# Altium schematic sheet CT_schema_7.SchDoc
size 430 x 429 mm
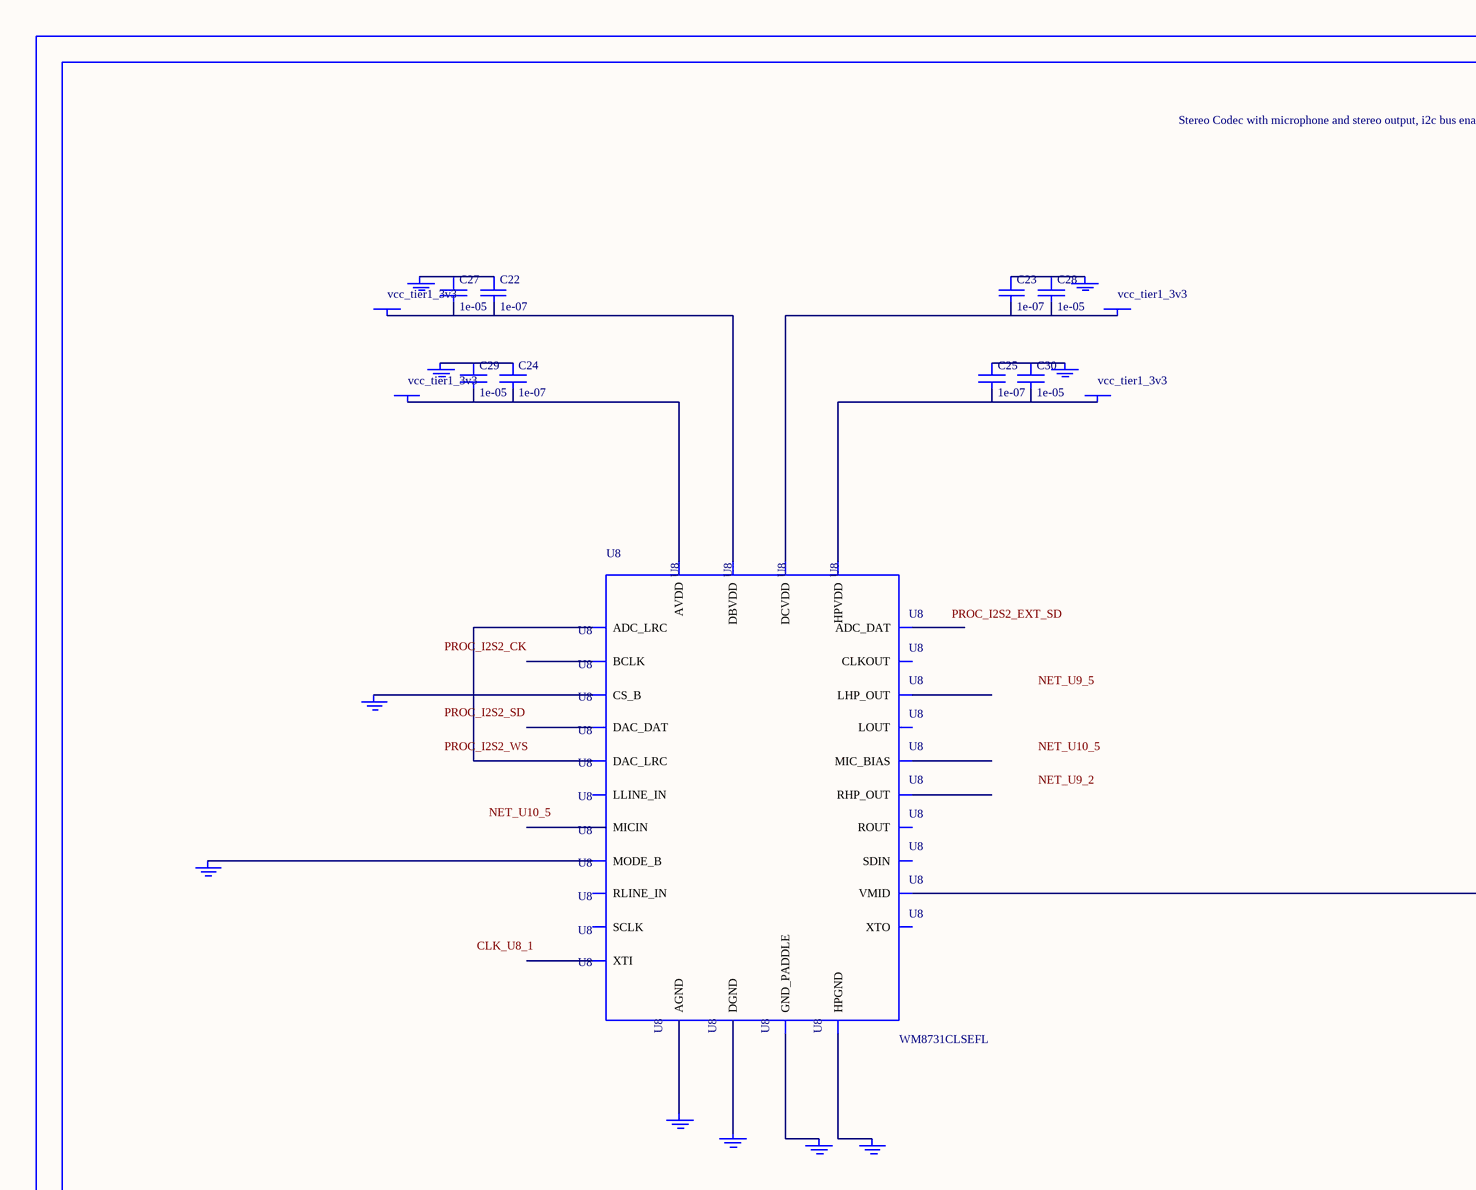
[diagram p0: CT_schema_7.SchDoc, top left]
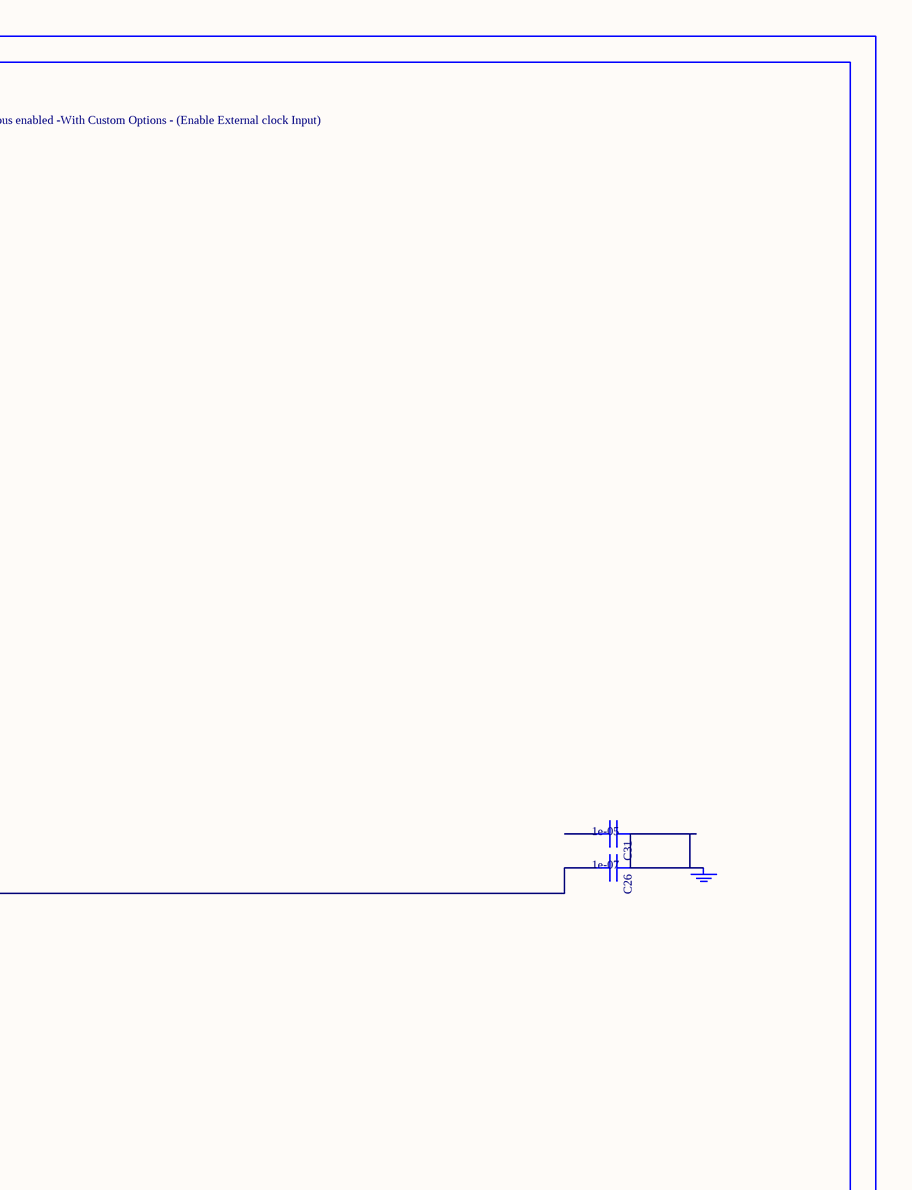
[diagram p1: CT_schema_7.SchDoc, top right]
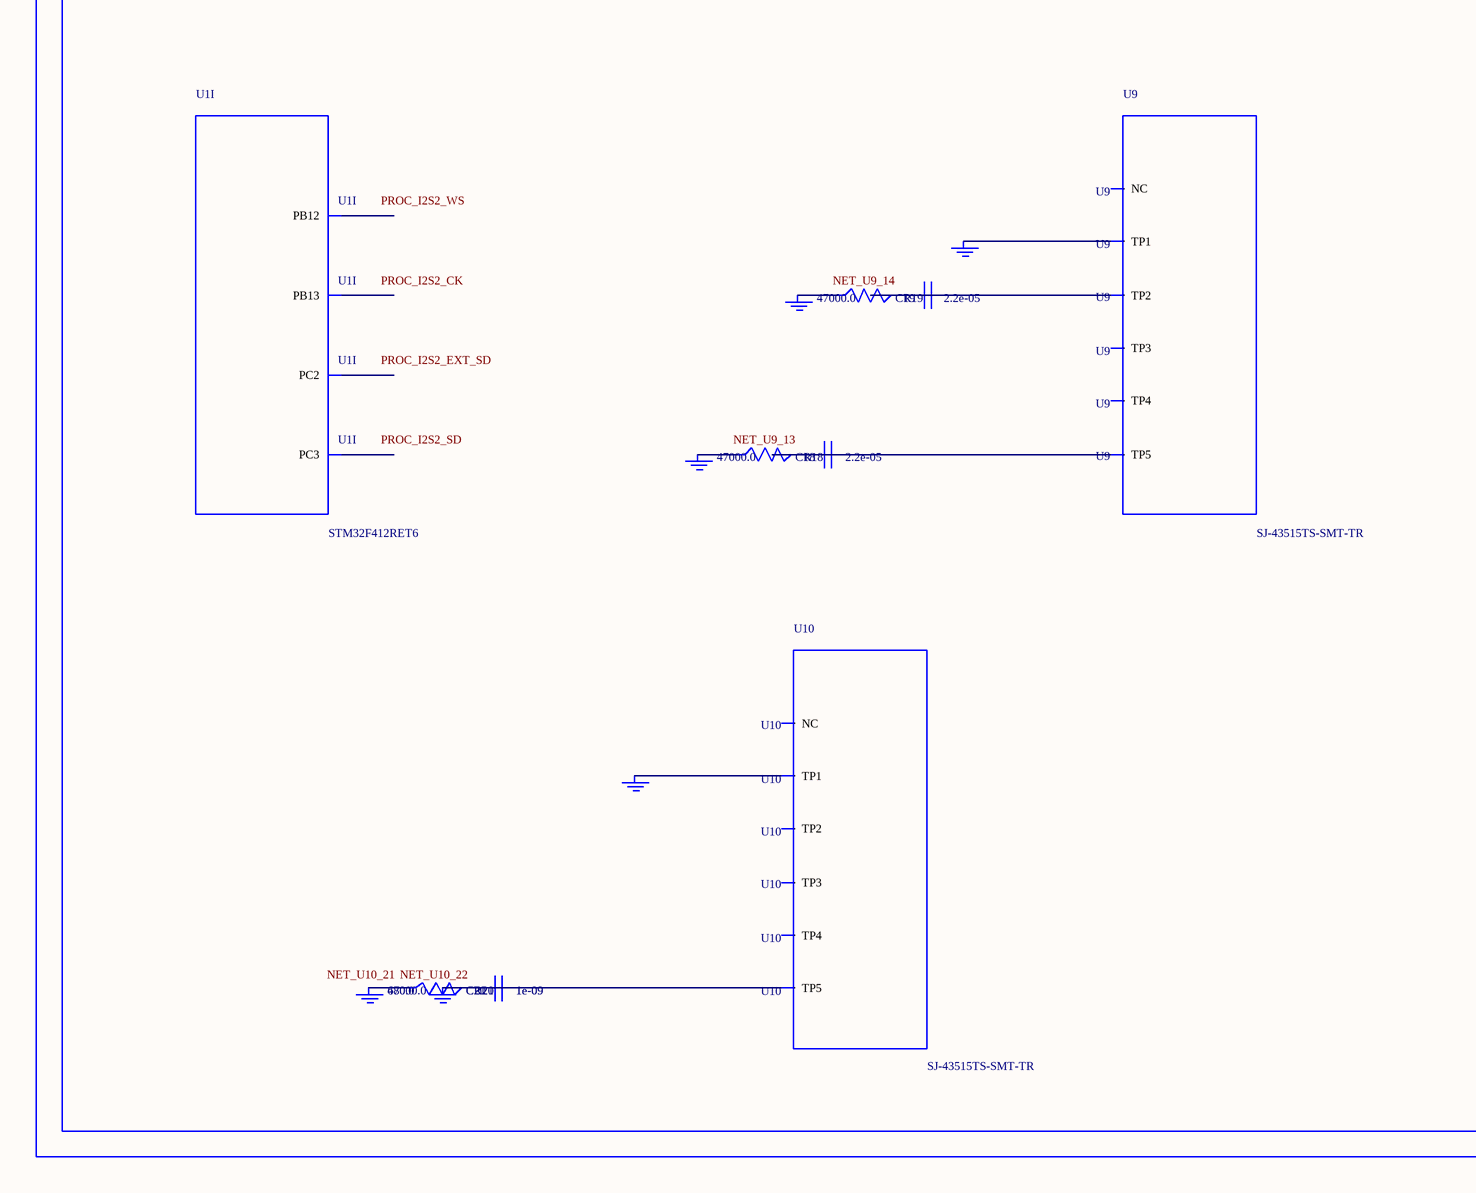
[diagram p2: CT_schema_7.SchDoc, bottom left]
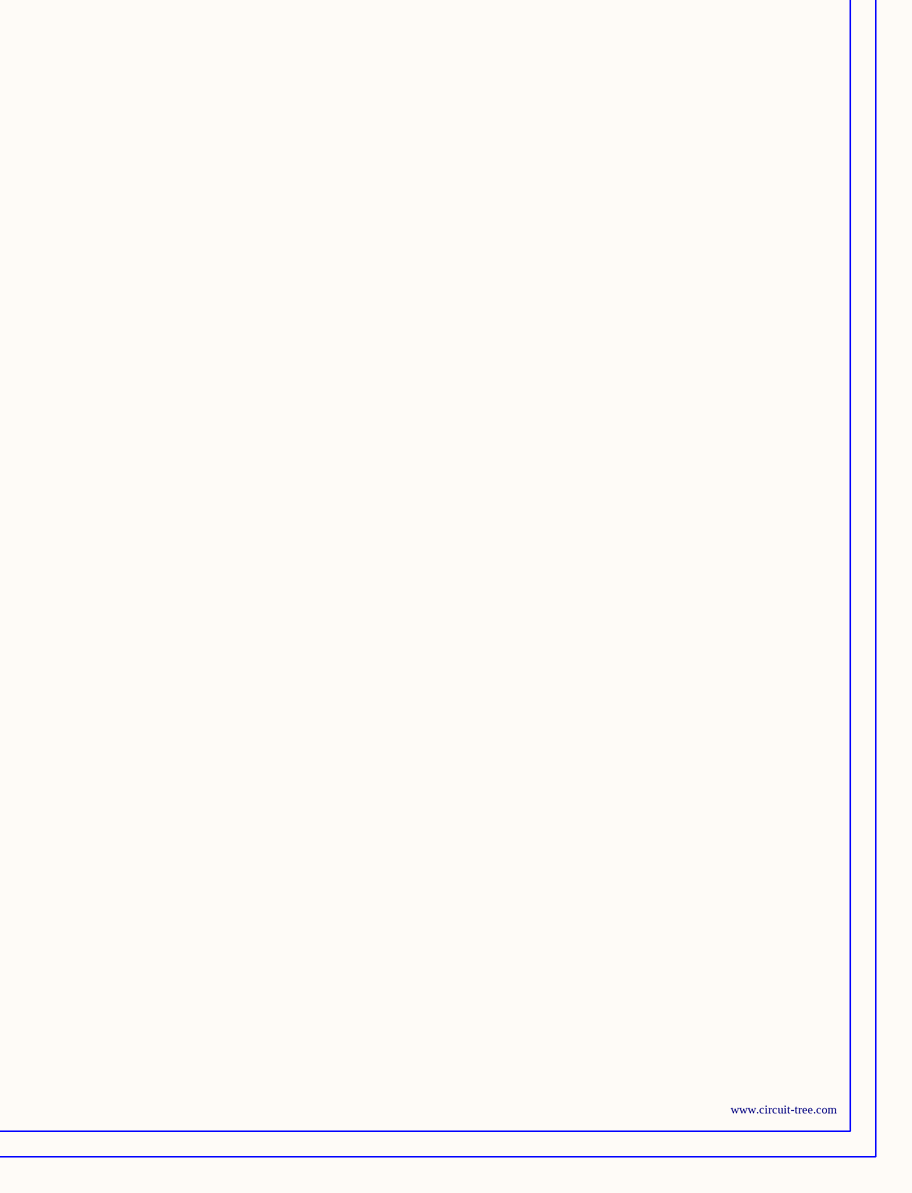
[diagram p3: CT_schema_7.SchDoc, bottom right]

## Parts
BORDER6  (no value)
C18  2.2e-05  [C1210]
C19  2.2e-05  [C1210]
C20  1e-09  [C0402]
C21  1e-09  [C0402]
C22  1e-07  [C0402]
C23  1e-07  [C0402]
C24  1e-07  [C0402]
C25  1e-07  [C0402]
C26  1e-07  [C0402]
C27  1e-05  [C0805]
C28  1e-05  [C0805]
C29  1e-05  [C0805]
C30  1e-05  [C0805]
C31  1e-05  [C0805]
GND_INSTANCE_6_0  (no value)
GND_INSTANCE_6_1  (no value)
GND_INSTANCE_6_2  (no value)
GND_INSTANCE_6_3  (no value)
GND_INSTANCE_6_4  (no value)
GND_INSTANCE_6_5  (no value)
GND_INSTANCE_6_6  (no value)
GND_INSTANCE_6_7  (no value)
GND_INSTANCE_6_8  (no value)
GND_INSTANCE_6_9  (no value)
GND_INSTANCE_6_10  (no value)
GND_INSTANCE_6_11  (no value)
GND_INSTANCE_6_12  (no value)
GND_INSTANCE_6_13  (no value)
GND_INSTANCE_6_14  (no value)
GND_INSTANCE_6_15  (no value)
GND_INSTANCE_6_16  (no value)
POWER_INSTANCE_6_0  vcc_tier1_3v3
POWER_INSTANCE_6_1  vcc_tier1_3v3
POWER_INSTANCE_6_2  vcc_tier1_3v3
POWER_INSTANCE_6_3  vcc_tier1_3v3
R18  47000.0  [R0603]
R19  47000.0  [R0603]
R20  47000.0  [R0603]
R21  680.0  [R0603]
U1  STM32F412RET6  [LQFP64]  (part I of 9)
U8  WM8731CLSEFL  [QFN-28]
U9  SJ-43515TS-SMT-TR  [SJ-43515TS-SMT-TR]
U10  SJ-43515TS-SMT-TR  [SJ-43515TS-SMT-TR]

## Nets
NetC18_1: C18.1 C18.2 R18.2 U9.5(TP5)
NetC19_1: C19.1 C19.2 R19.2 U9.2(TP2)
NetC20_1: C20.1 C20.2 C21.1 C21.2 GND_INSTANCE_6_16.0(GND) R20.2 R21.2 U10.5(TP5)
NetC22_1: C22.1 C27.1 GND_INSTANCE_6_1.0(GND)
NetC22_2: C22.2 C27.2 POWER_INSTANCE_6_1.0(PWR) U8.5(DBVDD)
NetC23_1: C23.1 C28.1 GND_INSTANCE_6_0.0(GND)
NetC23_2: C23.2 C28.2 POWER_INSTANCE_6_0.0(PWR) U8.3(DCVDD)
NetC24_1: C24.1 C29.1 GND_INSTANCE_6_4.0(GND)
NetC24_2: C24.2 C29.2 POWER_INSTANCE_6_3.0(PWR) U8.18(AVDD)
NetC25_1: C25.1 C30.1 GND_INSTANCE_6_2.0(GND)
NetC25_2: C25.2 C30.2 POWER_INSTANCE_6_2.0(PWR) U8.12(HPVDD)
NetC26_1: C26.1 C31.1 GND_INSTANCE_6_5.0(GND)
NetC26_2: C26.2 U8.20(VMID)
NetGND_INSTANCE_6_3_0: GND_INSTANCE_6_3.0(GND) U8.15(HPGND)
NetGND_INSTANCE_6_6_0: GND_INSTANCE_6_6.0(GND) U8.25(MODE_B)
NetGND_INSTANCE_6_7_0: GND_INSTANCE_6_7.0(GND) U8.26(CS_B)
NetGND_INSTANCE_6_8_0: GND_INSTANCE_6_8.0(GND) U8.29(GND_PADDLE)
NetGND_INSTANCE_6_9_0: GND_INSTANCE_6_9.0(GND) U8.4(DGND)
NetGND_INSTANCE_6_10_0: GND_INSTANCE_6_10.0(GND) U8.19(AGND)
NetGND_INSTANCE_6_11_0: GND_INSTANCE_6_11.0(GND) U9.1(TP1)
NetGND_INSTANCE_6_12_0: GND_INSTANCE_6_12.0(GND) R19.1
NetGND_INSTANCE_6_13_0: GND_INSTANCE_6_13.0(GND) R18.1
NetGND_INSTANCE_6_14_0: GND_INSTANCE_6_14.0(GND) U10.1(TP1)
NetGND_INSTANCE_6_15_0: GND_INSTANCE_6_15.0(GND) R20.1 R21.1
NetU8_9: U8.9(DAC_LRC) U8.11(ADC_LRC)

Not connected (* = marked no-connect by the designer): C31 2; U1 10(PC2) 11(PC3) 33(PB12) 34(PB13); U8 1(XTI) 2(XTO) 6(CLKOUT) 7(BCLK) 8(DAC_DAT) 10(ADC_DAT) 13(LHP_OUT) 14(RHP_OUT) 16(LOUT) 17(ROUT) 21(MIC_BIAS) 22(MICIN) 23(RLINE_IN) 24(LLINE_IN) 27(SDIN) 28(SCLK); U9 3(TP3) 4(TP4) 6(NC); U10 2(TP2) 3(TP3) 4(TP4) 6(NC)

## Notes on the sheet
- Labels drawn without touching a wire or pin: CLK_U8_1, NET_U9_2, NET_U9_5, NET_U9_13, NET_U9_14, NET_U10_5, NET_U10_21, NET_U10_22, PROC_I2S2_CK, PROC_I2S2_EXT_SD, PROC_I2S2_SD, PROC_I2S2_WS

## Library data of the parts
BORDER6 = BORDER_PAGE6
C18 C19 = C1210C224K5RACTU
C20 C21 = C0402C102K3RAC
C22-C26 = C0402C104K3RACTU
C27-C31 = C0805C106K8RACTU
GND_INSTANCE_6_0-GND_INSTANCE_6_16 = GND
POWER_INSTANCE_6_0-POWER_INSTANCE_6_3 = PWR
R18-R20 = RC0603JR-0747KL
R21 = RC0603JR-07680RL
